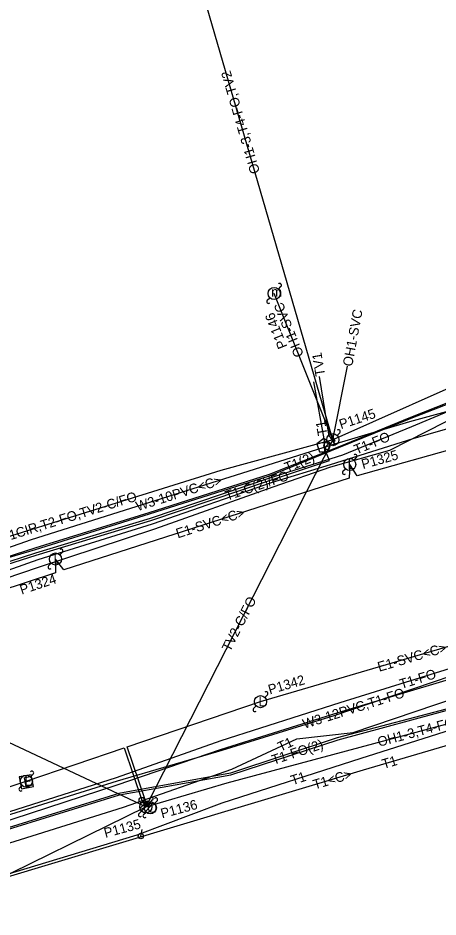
# Model space of a CAD drawing. Extents: x 2336688 to 2352634, y 362473 to 369571.
# Drawn here: x 2347005.5 to 2347179.1, y 367179.3 to 367550.3 of the extents above; entities that cross this region are included whole.
import ezdxf

# ---------------------------------------------------------------- set-up
doc = ezdxf.new("R2010")
doc.units = 0
for name, color, linetype in [('RD_EX_DV_Prop', 7, 'Continuous'), ('RD_EX_DV_TX_Prop', 7, 'Continuous'), ('RD_EX_RW', 7, 'Continuous'), ('RD_EX_RW_TX', 7, 'Continuous'), ('RD_HC_Data_Tic', 7, 'Continuous'), ('RD_PD_CstnLmt', 7, 'Continuous'), ('RD_PD_Final_TrvlWay', 7, 'Continuous'), ('RD_PD_PatLn4', 7, 'Continuous'), ('RD_SHT_ShtClip', 7, 'Continuous'), ('RD_Sketch2', 7, 'Continuous'), ('RD_Sketch5', 7, 'Continuous')]:
    doc.layers.add(name, color=color, linetype=linetype)

# ---------------------------------------------------------------- blocks, each defined once
blk = doc.blocks.new('GW')
at = {"layer": 'RD_HC_Data_Tic'}
blk.add_line((0, 0), (0, 5), dxfattribs=at)
blk.add_circle((0, 0), 2, dxfattribs=at)

msp = doc.modelspace()

# ---------------------------------------------------------------- linework, layer by layer
at = {"layer": 'RD_EX_RW_TX'}
msp.add_line((2346913.35, 367169.48), (2347148.27, 367240), dxfattribs=at)
for points in [[(2347493.21, 367479.93), (2347455.71, 367473.66), (2347452.74, 367474.1), (2347448.74, 367473.85), (2347412.51, 367459.94), (2347396.43, 367453.77), (2347382.64, 367448.58), (2347379.12, 367448.82), (2347347.7, 367441.05), (2347301.35, 367428.58), (2347253.11, 367413.66), (2347204.34, 367396.75), (2347168.08, 367381.62), (2347139.54, 367369.91), (2347109.42, 367360.33), (2347060.14, 367343.81), (2347012.82, 367329.5), (2346964.23, 367313.72), (2346893.43, 367288.42), (2346890.71, 367286.97), (2346887.9, 367286.45), (2346775.81, 367246.88), (2346756.05, 367240.68)], [(2347493.07, 367480.59), (2347455.62, 367474.3), (2347452.74, 367474.1), (2347450.17, 367472.02), (2347413.02, 367459.45), (2347396.97, 367451.28), (2347348.05, 367437.46), (2347302.76, 367423.98), (2347255.28, 367408.11), (2347207.74, 367387.96), (2347168.62, 367376.63), (2347134.49, 367365.89), (2347110.11, 367358.5), (2347060.95, 367341.47), (2347013.68, 367326.75), (2346965.57, 367309.6), (2346919.17, 367294.2), (2346889.18, 367289.05), (2346836.21, 367315.04), (2346827.9, 367322.52), (2346822.65, 367340.13), (2346824.21, 367344.56)], [(2347493.75, 367473.66), (2347444.81, 367465.06), (2347396.07, 367455.9), (2347345.96, 367442.69), (2347300.78, 367430.21), (2347252.72, 367414.9), (2347203.98, 367399.02), (2347167.78, 367385.01), (2347137.95, 367372.86), (2347109.32, 367361.19), (2347059.71, 367345.57), (2347012.57, 367330.88), (2346963.45, 367316.33), (2346917.8, 367299.85), (2346891.73, 367292.36), (2346839.33, 367318.15), (2346829.05, 367325.03), (2346824.09, 367341.03), (2346824.21, 367344.56)], [(2347493.77, 367474.07), (2347444.64, 367465.68), (2347395.98, 367456.43), (2347345.81, 367443.17), (2347300.67, 367430.69), (2347252.46, 367415.35), (2347204.25, 367399.86), (2347167.66, 367385.47), (2347137.74, 367373.17), (2347109.3, 367361.85), (2347059.64, 367346.11), (2347012.51, 367331.46), (2346963.58, 367315.78), (2346917.62, 367300.41), (2346891.78, 367293.28), (2346839.99, 367318.61), (2346831.68, 367325.52), (2346825.4, 367341.75), (2346824.21, 367344.56)], [(2347135.6, 367376.27), (2347134.12, 367377.66), (2347130.04, 367402.33)], [(2346744.36, 367255.92), (2346762.03, 367276.39), (2346781.92, 367298.77), (2346814.85, 367333.98), (2346822.42, 367342.26), (2346824.21, 367344.56), (2346823.39, 367341.4), (2346828.52, 367324.89), (2346836.66, 367315.73), (2346889.46, 367289.94), (2346918.72, 367296.97), (2346964.46, 367313.14), (2347013.05, 367328.63), (2347060.47, 367342.93), (2347109.88, 367359.54), (2347134.28, 367367.62), (2347132.27, 367372.32), (2347131.88, 367373.69), (2347132.25, 367375.15), (2347127.72, 367400.1)], [(2346929.43, 366898.3), (2346926.24, 366950.27), (2346914.94, 366994.66), (2346903.95, 367048.72), (2346891.88, 367094.98), (2346882.43, 367148.75), (2346880.23, 367164.03), (2346885.05, 367187.76), (2346886.25, 367192.23), (2346889.58, 367192.85), (2346896.67, 367193.51), (2346947.77, 367206.59), (2346995.79, 367219.64), (2347046.69, 367235.53), (2347089.94, 367248.15), (2347136.19, 367262.43), (2347184.88, 367278.93), (2347230.19, 367297.47), (2347271.77, 367311.28), (2347325.01, 367320.63), (2347375.99, 367328.45), (2347424.9, 367338.06), (2347468.18, 367347.3), (2347525.21, 367359.4)], [(2346729.92, 367125.44), (2346760.09, 367132.46), (2346822.83, 367150.8), (2346847.92, 367159.43), (2346911.38, 367177.91), (2346957.67, 367191.14), (2346999.5, 367209.08), (2347049.12, 367224.56), (2347093.92, 367240.35), (2347120.7, 367252.77), (2347143.99, 367255.5), (2347186.71, 367269.91), (2347236.58, 367285.94), (2347255.06, 367289.24), (2347276.57, 367291.67), (2347281.58, 367292.99), (2347300.77, 367298.26), (2347328.04, 367305.43), (2347378.49, 367318.88), (2347428.36, 367324.58), (2347471.76, 367333.48), (2347528.47, 367342.27)], [(2346897.18, 367161.87), (2346897.33, 367167.15), (2346913.45, 367172.96), (2346960.85, 367184.91), (2347003.36, 367197.72), (2347054.81, 367213.14), (2347089.91, 367226.4), (2347147.29, 367244.91), (2347193.34, 367259.48), (2347243.62, 367272.38), (2347257.76, 367276.24), (2347278.69, 367281.44), (2347302.95, 367288.88), (2347331.85, 367293.13), (2347381.23, 367305.16), (2347429.75, 367317.72), (2347473.23, 367326.64), (2347527.97, 367334.66)], [(2347184.08, 367281.81), (2347138.56, 367267.72), (2347089.38, 367252.03), (2347046.03, 367236.73), (2346995.36, 367220.65), (2346947.88, 367207.83), (2346896.65, 367195.02), (2346889.86, 367192.06), (2346888.13, 367190.49), (2346885.89, 367189.55), (2346877.25, 367185.04), (2346875.24, 367162.99), (2346879.34, 367145.21), (2346889.15, 367095.18), (2346897.75, 367046.5), (2346908.64, 366996.35), (2346918.58, 366948.75), (2346927.75, 366898.93)], [(2347148.27, 367240), (2347194.65, 367253.63), (2347238.25, 367267.08), (2347241.57, 367265.57), (2347262.35, 367165.72), (2347268.45, 367119.85), (2347270.43, 367112.95), (2347273.7, 367113.96), (2347276.05, 367114.24), (2347274.41, 367113.29), (2347270.48, 367108.09), (2347263.45, 367101.7), (2347250.15, 367097.15)], [(2347187.63, 367266.43), (2347137.4, 367253.23), (2347093.35, 367238.65), (2347047.24, 367230.28), (2346997.39, 367214.83), (2346954.54, 367201.39), (2346927.39, 367190.56), (2346910.36, 367183.58), (2346900.58, 367182.36), (2346891.43, 367181.19), (2346845.03, 367169.9), (2346819.99, 367162.67), (2346802.3, 367157.83), (2346797.35, 367156.24), (2346793.14, 367153.5), (2346783.01, 367146.37), (2346758.96, 367136.25)], [(2346759.16, 367135.67), (2346783.33, 367145.57), (2346793.56, 367152.89), (2346797.35, 367156.24), (2346802.42, 367157.05), (2346820.18, 367162.16), (2346845.16, 367169.26), (2346891.6, 367180.39), (2346900.69, 367181.78), (2346910.69, 367182.74), (2346927.88, 367189.94), (2346954.81, 367201.03), (2346997.5, 367214.34), (2347047.41, 367229.71), (2347093.48, 367238.02), (2347137.76, 367252.45), (2347187.57, 367265.92)]]:
    msp.add_lwpolyline(points, dxfattribs=at)
msp.add_lwpolyline([(2347131.88, 367376.69), (2347129.02, 367374.62), (2347130.11, 367371.26), (2347133.64, 367371.26), (2347134.73, 367374.62)], close=True, dxfattribs=at)
at = {"layer": 'RD_HC_Data_Tic'}
for p, q in [((2347113.11, 367438.39), (2347114.17, 367439.45)), ((2347108.51, 367433.79), (2347109.57, 367434.85)), ((2347137.37, 367378.03), (2347138.43, 367379.09)), ((2347132.77, 367373.44), (2347133.83, 367374.5)), ((2347144.35, 367367.83), (2347145.41, 367368.89)), ((2347139.75, 367363.23), (2347140.81, 367364.29)), ((2347022.8, 367328.78), (2347023.86, 367329.85)), ((2347018.2, 367324.19), (2347019.26, 367325.25)), ((2347107.49, 367269.92), (2347108.55, 367270.99)), ((2347102.89, 367265.33), (2347103.95, 367266.39)), ((2347010.73, 367237.14), (2347011.79, 367238.2)), ((2347006.13, 367232.55), (2347007.19, 367233.61)), ((2347055.92, 367224.11), (2347058.98, 367227.17)), ((2347056.57, 367222.99), (2347060.1, 367226.52)), ((2347060.1, 367226.52), (2347061.16, 367227.59)), ((2347061.95, 367226.13), (2347063.01, 367227.19)), ((2347055.51, 367221.93), (2347056.57, 367222.99)), ((2347057.36, 367221.54), (2347058.42, 367222.6)), ((2347057.69, 367222.34), (2347060.75, 367225.4))]:
    msp.add_line(p, q, dxfattribs=at)
msp.add_lwpolyline([(2347135.2, 367378.27), (2347136.03, 367376.26), (2347134.57, 367377.06), (2347136.45, 367374.38), (2347136.45, 367374.38), (2347135.25, 367376.48), (2347136.63, 367375.67)], close=True, dxfattribs=at)
for centre in [(2347111.34, 367436.62), (2347135.6, 367376.27), (2347142.58, 367366.06), (2347021.03, 367327.02), (2347105.72, 367268.16), (2347008.96, 367235.37), (2347058.33, 367224.76), (2347060.19, 367224.36)]:
    msp.add_circle(centre, 2.5, dxfattribs=at)
for centre, start, end in [((2347113.64, 367439.98), 315, 135), ((2347109.04, 367433.26), 135, 315), ((2347137.9, 367379.62), 315, 135), ((2347133.3, 367372.91), 135, 315), ((2347144.88, 367369.42), 315, 135), ((2347140.28, 367362.7), 135, 315), ((2347023.33, 367330.38), 315, 135), ((2347018.73, 367323.66), 135, 315), ((2347108.02, 367271.52), 315, 135), ((2347103.42, 367264.8), 135, 315), ((2347011.26, 367238.73), 315, 135), ((2347006.66, 367232.02), 135, 315), ((2347060.63, 367228.12), 315, 135), ((2347062.48, 367227.72), 315, 135), ((2347056.04, 367221.4), 135, 315), ((2347057.89, 367221.01), 135, 315)]:
    msp.add_arc(centre, 0.75, start, end, dxfattribs=at)
at = {"layer": 'RD_PD_Final_TrvlWay'}
for points in [[(2347365.04, 367648.59), (2347375.04, 367646.81), (2347420.85, 367453.86), (2347411.66, 367432.11), (2347408.65, 367425.96), (2347247.09, 367389.8), (2347245.57, 367389.37), (2347243.03, 367393.87), (2347242.83, 367388.6), (2347145.71, 367361.39), (2347142.58, 367366.06), (2347142.34, 367360.37), (2347024.46, 367322.51), (2347021.03, 367327.02), (2347021.01, 367321.39), (2346880.04, 367274.9), (2346876.34, 367279.3), (2346876.12, 367273.62), (2346794.47, 367247.23), (2346765.54, 367237.88), (2346760.44, 367241.84)], [(2346900.17, 367199.42), (2347008.96, 367235.37), (2347049.36, 367249.06), (2347056.78, 367227.15), (2347058.33, 367224.76), (2347058.11, 367227.6), (2347050.69, 367249.51), (2347105.72, 367268.16), (2347228.62, 367304.26)]]:
    msp.add_lwpolyline(points, dxfattribs=at)
msp.add_lwpolyline([(2347010.97, 367238.02), (2347006.06, 367237.1), (2347006.98, 367232.19), (2347011.89, 367233.11)], close=True, dxfattribs=at)
at = {"layer": 'RD_SHT_ShtClip'}
for p, q in [((2347135.6, 367376.27), (2347059.16, 367638.64)), ((2347135.6, 367376.27), (2347111.34, 367436.62)), ((2347135.6, 367376.27), (2347141.61, 367406.64)), ((2347135.6, 367376.27), (2347058.33, 367224.76)), ((2347058.33, 367224.76), (2346894.69, 367301.37))]:
    msp.add_line(p, q, dxfattribs=at)
for points in [[(2347408.44, 367465.79), (2347339.72, 367450.68), (2347199.91, 367404.81), (2347135.6, 367376.27)], [(2347135.6, 367376.27), (2347089.3, 367363.5), (2346940.06, 367317.1), (2346894.69, 367301.37)], [(2347058.33, 367224.76), (2347091.91, 367234.67), (2347300.5, 367290.46), (2347334.55, 367298.63)], [(2346809.48, 367136.35), (2346886.82, 367154.19), (2346987.08, 367189.8), (2347058.33, 367224.76)]]:
    msp.add_lwpolyline(points, dxfattribs=at)
at = {"layer": 'RD_Sketch2'}
for points in [[(2347134.18, 367373.81), (2347167.37, 367383.79), (2347232.91, 367401.6), (2347255.39, 367407.5), (2347299.78, 367416.9), (2347348.96, 367428.56), (2347400.21, 367440.41), (2347447.52, 367449.07), (2347449.95, 367449.7), (2347496.38, 367458.28)], [(2347011.15, 367335.04), (2347134.18, 367373.81)], [(2346907.18, 367191.36), (2346908.2, 367188.48), (2346918.67, 367191.57), (2346952.96, 367203.21), (2346996.26, 367217.42), (2347046.54, 367233.83), (2347089.24, 367248.48), (2347137.8, 367263.72), (2347185.19, 367277.87), (2347233.41, 367292.66), (2347283.51, 367309.44), (2347303.65, 367314.93), (2347326.25, 367319.14), (2347377.74, 367324.63), (2347405.39, 367327.95), (2347438.97, 367330.87), (2347470.35, 367337.23), (2347531.2, 367351.47)], [(2346970.59, 367320.92), (2347011.15, 367335.04)]]:
    msp.add_lwpolyline(points, dxfattribs=at)
at = {"layer": 'RD_Sketch5'}
msp.add_lwpolyline([(2346889.8, 367282.74), (2346919.7, 367292.87), (2346965.73, 367307.3), (2347014.03, 367323.63), (2347062.01, 367339.53), (2347111.01, 367356.83), (2347134.82, 367365.07), (2347159.13, 367371.92), (2347205.14, 367395.36), (2347226.9, 367411.47), (2347251.72, 367417.37), (2347346.28, 367442.06), (2347396.34, 367454.61), (2347445.27, 367463.42), (2347494.44, 367469.25)], dxfattribs=at)

# ---------------------------------------------------------------- block references
at = {"layer": 'RD_HC_Data_Tic', "xscale": 0.5546771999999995, "yscale": 0.5546771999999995}
for p, rotation in [((2347056.64, 367227.55), -135.0179140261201), ((2347056.27, 367212.67), -10.59006546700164)]:
    msp.add_blockref('GW', p, dxfattribs=dict(at, rotation=rotation))

# ---------------------------------------------------------------- texts
at = {"layer": 'RD_EX_DV_Prop'}
for rotation, p in [(17.8065, (2347071.54, 367335.53)), (16.3721, (2347154.75, 367280.48))]:
    msp.add_text('E1-SVC<C>', height=4, rotation=rotation, dxfattribs=at).set_placement(p)
at = {"layer": 'RD_EX_DV_TX_Prop'}
for s, rotation, p in [('P1146', 111.8971, (2347116.9, 367414.73)), ('P1145', 18.1651, (2347138.97, 367380.58)), ('P1325', 15.652, (2347148.06, 367364.11)), ('P1324', 18.2511, (2347007.06, 367312.31)), ('P1342', 16.3203, (2347109.56, 367271.11)), ('P1136', 14.9737, (2347065.08, 367219.99)), ('P1135', 14.9737, (2347041.66, 367211.95))]:
    msp.add_text(s, height=4, rotation=rotation, dxfattribs=at).set_placement(p)
at = {"layer": 'RD_EX_RW'}
for s, rotation, p in [('TV1', 99.3949, (2347132.46, 367402.8)), ('T1', 100.2814, (2347133.43, 367378.34)), ('T1-FO', 22.3052, (2347145.35, 367370.13)), ('T1(2)', 21.6971, (2347116.59, 367362.8)), ('T1-C(2)/FO', 18.5823, (2347091.87, 367351.06)), ('T1-FO', 17.2028, (2347163.89, 367273.38)), ('T1-FO', 17.5635, (2347150.86, 367265.47)), ('T1-FO(2)', 18.0475, (2347111.12, 367242.11)), ('T1', 24.8818, (2347113.94, 367247.44)), ('T1', 16.3691, (2347156.57, 367240.36)), ('T1', 17.8745, (2347118.95, 367233.67)), ('T1<C>', 16.7097, (2347128.13, 367231.87))]:
    msp.add_text(s, height=4, rotation=rotation, dxfattribs=at).set_placement(p)
at = {"layer": 'RD_EX_RW_TX'}
msp.add_text('T', height=3.75, dxfattribs=at).set_placement((2347130.65, 367371.46))
at = {"layer": 'RD_HC_Data_Tic'}
for s, p in [('m', (2347110.16, 367435.29)), ('L', (2347141.77, 367364.12)), ('L', (2347020.22, 367325.08)), ('L', (2347104.91, 367266.22)), ('L', (2347008.15, 367233.44))]:
    msp.add_text(s, height=4, rotation=360, dxfattribs=at).set_placement(p)
msp.add_text('O', height=4, dxfattribs=at).set_placement((2347058.89, 367222.36))
at = {"layer": 'RD_PD_CstnLmt'}
for s, rotation, p in [('W3-10PVC<C>', 17.4906, (2347054.97, 367346.75)), ('W3-12PVC,', 17.5635, (2347123.88, 367256.93))]:
    msp.add_text(s, height=4, rotation=rotation, dxfattribs=at).set_placement(p)
at = {"layer": 'RD_PD_Final_TrvlWay'}
msp.add_text('E', height=4, rotation=10.6261, dxfattribs=at).set_placement((2347008.15, 367232.91))
at = {"layer": 'RD_PD_PatLn4'}
for s, rotation, p in [('OH1-3,T4-FO,TV2', 106.2422, (2347105.52, 367486.66)), ('OH1-SVC', 111.8971, (2347123.69, 367411.26)), ('OH1-SVC', 79.4641, (2347143.58, 367406.27)), ('OH1-3,OH2-1CIR,T2-FO,TV2-C/FO', 17.269, (2346973.86, 367325.91)), ('TV2-C/FO', 62.9799, (2347093.1, 367288.52)), ('OH1-3,T4-FO,TV1-C/FO,TV2-C/FO', 14.9737, (2347154.68, 367249.52))]:
    msp.add_text(s, height=4, rotation=rotation, dxfattribs=at).set_placement(p)

doc.saveas('drawing.dxf')
